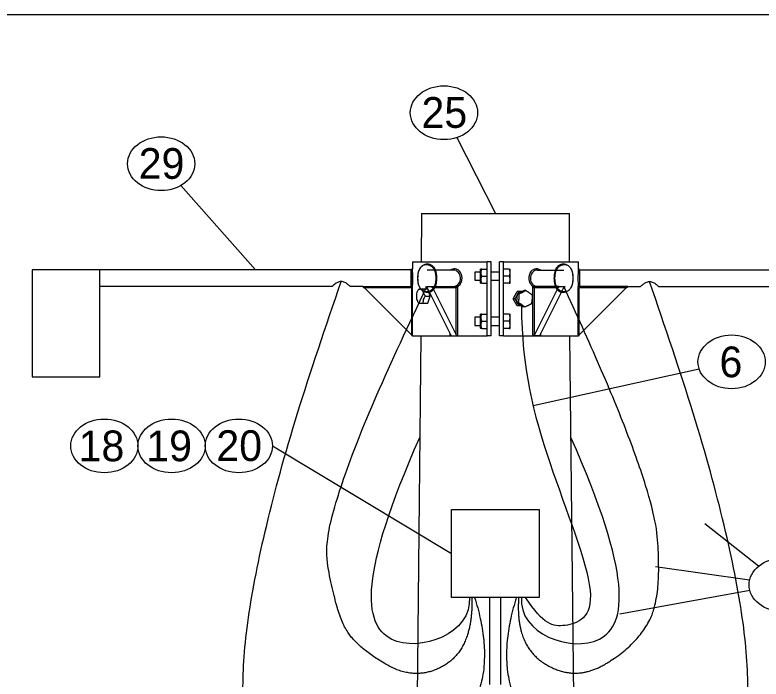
# Model space of a CAD drawing. Extents: x 99862 to 104211, y 98939 to 102076.
# Drawn here: x 101620.5 to 102008.9, y 101729.8 to 102075.5 of the extents above; entities that cross this region are included whole.
import ezdxf

# ---------------------------------------------------------------- set-up
doc = ezdxf.new("R2010")
doc.units = 0
for name, color, linetype in [('Level 1', 7, 'Continuous'), ('Level 11', 7, 'Continuous'), ('Level 15', 7, 'Continuous'), ('Level 2', 7, 'Continuous'), ('Level 20', 7, 'Continuous'), ('Level 3', 7, 'Continuous'), ('Level 4', 7, 'Continuous'), ('Level 7', 7, 'Continuous'), ('Level 8', 7, 'Continuous'), ('Level 9', 7, 'Continuous')]:
    doc.layers.add(name, color=color, linetype=linetype)

msp = doc.modelspace()

# ---------------------------------------------------------------- linework, layer by layer
at = {"layer": 'Level 1'}
for p, q in [((101832.05, 101972.17), (101831.95, 101947.03)), ((101832.05, 101972.17), (101909.09, 101972.17)), ((101909.19, 101947.03), (101909.09, 101972.17)), ((101831.83, 101908.51), (101827.97, 101553.5)), ((101913.17, 101553.5), (101909.31, 101908.51))]:
    msp.add_line(p, q, dxfattribs=at)
msp.add_lwpolyline([(99862, 99999.5), (103151, 99999.5), (103151, 102075.5), (99862, 102075.5)], close=True, dxfattribs=at)
at = {"layer": 'Level 11'}
for points, degree in [([(101859.74, 101772.33), (101884.78, 101693.2), (101689.65, 101651.83), (101790.32, 101936.72)], 2), ([(101881.51, 101772.33), (101856.36, 101693.2), (102051.49, 101651.83), (101950.83, 101936.72)], 2), ([(101858.36, 101772.33), (101858.98, 101746.11), (101829.7, 101728.16), (101798.23, 101746.36), (101787.55, 101764.66), (101778.43, 101817.11), (101834.87, 101934.19)], 2), ([(101882.71, 101772.33), (101880.76, 101747.64), (101911.44, 101728.16), (101942.91, 101746.36), (101957.57, 101772.16), (101952.13, 101835.35), (101906.16, 101934.19)], 2), ([(101884.15, 101924.06), (101884.15, 101891.84), (101896.5, 101843.69), (101929.3, 101764.2), (101905.32, 101755.78), (101895.6, 101758), (101886.26, 101772.33)], 3), ([(101857.02, 101772.33), (101858.73, 101753.77), (101803.63, 101732.32), (101799.57, 101784.11), (101831.25, 101855.61)], 3), ([(101884.12, 101772.33), (101882.41, 101753.77), (101937.51, 101732.32), (101941.57, 101784.11), (101909.89, 101855.61)], 3)]:
    msp.add_open_spline(points, degree=degree, dxfattribs=at)
at = {"layer": 'Level 15'}
for p, q in [((101850.42, 102011.63), (101870.57, 101972.17)), ((101706.78, 101986.65), (101745.76, 101942.73)), ((101976.65, 101891.16), (101890.19, 101872.03)), ((101754.53, 101851.16), (101847.74, 101795.16)), ((102007.48, 101788.47), (101979.58, 101810.64)), ((102002.91, 101781.22), (101953.92, 101788.27)), ((102003.06, 101775.81), (101935.37, 101763.54))]:
    msp.add_line(p, q, dxfattribs=at)
at = {"layer": 'Level 2'}
for p, q in [((101827.35, 101947.03), (101866.31, 101947.03)), ((101827.35, 101947.03), (101827.35, 101943.27)), ((101866.31, 101908.51), (101866.31, 101947.03)), ((101868.44, 101947.03), (101866.31, 101947.03)), ((101868.44, 101908.51), (101868.44, 101947.03)), ((101874.83, 101947.03), (101872.7, 101947.03)), ((101872.7, 101908.51), (101872.7, 101947.03)), ((101874.83, 101908.51), (101874.83, 101947.03)), ((101874.83, 101947.03), (101913.79, 101947.03)), ((101913.79, 101943.27), (101913.79, 101947.03)), ((101827.39, 101908.51), (101866.31, 101908.51)), ((101868.44, 101908.51), (101866.31, 101908.51)), ((101874.83, 101908.51), (101872.7, 101908.51)), ((101874.83, 101908.51), (101913.75, 101908.51))]:
    msp.add_line(p, q, dxfattribs=at)
for points in [[(101827.41, 101934.19), (101827.41, 101934.22), (101827.42, 101934.26), (101827.48, 101934.93), (101827.57, 101936.02), (101827.63, 101938.44), (101827.61, 101939.78), (101827.49, 101941.96), (101827.41, 101942.79), (101827.36, 101943.21), (101827.35, 101943.26), (101827.36, 101943.26)], [(101913.79, 101943.27), (101913.78, 101943.27), (101913.74, 101942.86), (101913.61, 101941.32), (101913.54, 101940.11), (101913.51, 101937.59), (101913.56, 101936.31), (101913.66, 101934.87), (101913.7, 101934.48), (101913.73, 101934.19)]]:
    msp.add_open_spline(points, degree=3, dxfattribs=at)
at = {"layer": 'Level 20'}
for centre in [(101843.8, 102024.59), (101696.61, 101998.05), (101993.52, 101894.89), (101667.03, 101851.16), (101702.03, 101851.16), (101737.03, 101851.16), (102020.15, 101778.82)]:
    msp.add_ellipse(centre, major_axis=(-17.5, 0), ratio=0.8, dxfattribs=at)
at = {"layer": 'Level 3'}
for p, q in [((101802.3, 101933.56), (101826.89, 101908.98)), ((101834.98, 101934.19), (101837.53, 101934.19)), ((101837.81, 101933.58), (101850.15, 101908.9)), ((101903.33, 101933.58), (101890.99, 101908.91)), ((101903.61, 101934.19), (101906.16, 101934.19)), ((101938.84, 101933.56), (101914.25, 101908.98)), ((101847.58, 101908.51), (101850.35, 101908.51)), ((101850.31, 101908.59), (101850.35, 101908.51)), ((101893.56, 101908.51), (101890.79, 101908.51))]:
    msp.add_line(p, q, dxfattribs=at)
for points in [[(101801.68, 101934.19), (101801.68, 101934.19), (101801.68, 101934.18)], [(101834.77, 101934.19), (101834.74, 101934.19), (101847.58, 101908.51)], [(101906.4, 101934.19), (101906.4, 101934.19), (101893.56, 101908.51)], [(101939.46, 101934.19), (101939.46, 101934.19), (101939.46, 101934.18)]]:
    msp.add_lwpolyline(points, dxfattribs=at)
at = {"layer": 'Level 4'}
for p, q in [((101664.73, 101934.19), (101664.73, 101942.73)), ((101826.82, 101942.73), (101664.73, 101942.73)), ((101826.82, 101934.19), (101826.82, 101942.71)), ((101848.69, 101942.71), (101834.98, 101942.71)), ((101892.44, 101942.71), (101906.16, 101942.71)), ((102076.41, 101942.71), (101914.32, 101942.71)), ((101785.6, 101934.19), (101664.73, 101934.19)), ((101801.68, 101934.19), (101795.03, 101934.19)), ((101939.46, 101934.19), (101946.12, 101934.19)), ((101955.55, 101934.19), (102076.41, 101934.19))]:
    msp.add_line(p, q, dxfattribs=at)
msp.add_lwpolyline([(101664.73, 101942.73), (101629.43, 101942.73), (101629.43, 101887.1), (101664.73, 101887.1)], close=True, dxfattribs=at)
for centre, major_axis, ratio, start_param, end_param in [((101848.69, 101938.44), (0, -4.27), 0.864412, 0.086361, 3.141601), ((101892.45, 101938.45), (0, -4.26), 0.866025, 3.217899, 6.283177), ((101892.45, 101938.45), (0, -4.26), 0.866025, 3.141593, 3.217899)]:
    msp.add_ellipse(centre, major_axis=major_axis, ratio=ratio, start_param=start_param, end_param=end_param, dxfattribs=at)
for points, degree in [([(101839.9, 101938.45), (101839.9, 101946.98), (101830.06, 101946.98), (101830.06, 101938.45), (101830.06, 101929.93), (101839.9, 101929.93), (101839.9, 101938.45)], 4), ([(101830.26, 101938.45), (101830.26, 101930.27), (101839.71, 101930.27), (101839.71, 101938.45), (101839.71, 101946.63), (101830.26, 101946.63), (101830.26, 101938.45)], 4), ([(101901.24, 101938.45), (101901.24, 101929.93), (101911.08, 101929.93), (101911.08, 101938.45), (101911.08, 101946.98), (101901.24, 101946.98), (101901.24, 101938.45)], 4), ([(101910.88, 101938.45), (101910.88, 101946.63), (101901.43, 101946.63), (101901.43, 101938.45), (101901.43, 101930.27), (101910.88, 101930.27), (101910.88, 101938.45)], 4), ([(101795.03, 101934.19), (101795.04, 101934.19), (101795.04, 101934.19), (101795.04, 101934.19), (101794.9, 101934.31), (101794.42, 101934.73), (101794.08, 101935.02), (101793.25, 101935.64), (101792.75, 101935.98), (101791.63, 101936.52), (101790.98, 101936.72), (101789.65, 101936.72), (101788.99, 101936.52), (101787.87, 101935.98), (101787.38, 101935.64), (101786.14, 101934.71), (101785.6, 101934.19), (101785.6, 101934.19)], 3), ([(101946.11, 101934.19), (101946.11, 101934.19), (101946.11, 101934.19), (101946.11, 101934.19), (101946.24, 101934.31), (101946.72, 101934.73), (101947.07, 101935.02), (101947.9, 101935.64), (101948.39, 101935.98), (101949.51, 101936.52), (101950.16, 101936.72), (101951.5, 101936.72), (101952.14, 101936.52), (101953.27, 101935.98), (101953.76, 101935.65), (101955.01, 101934.71), (101955.55, 101934.19), (101955.55, 101934.19)], 3)]:
    msp.add_open_spline(points, degree=degree, dxfattribs=at)
at = {"layer": 'Level 7'}
for p, q in [((101859.85, 101941.64), (101859.85, 101937.42)), ((101862.9, 101941.64), (101859.85, 101941.64)), ((101862.96, 101943.24), (101862.9, 101943.17)), ((101862.9, 101935.89), (101862.9, 101943.17)), ((101863.46, 101943.24), (101866.31, 101943.24)), ((101872.7, 101941.64), (101868.44, 101941.64)), ((101877.68, 101943.24), (101874.83, 101943.24)), ((101878.24, 101943.17), (101878.18, 101943.24)), ((101878.24, 101935.89), (101878.24, 101943.17)), ((101859.85, 101937.42), (101859.85, 101937.42)), ((101859.85, 101937.42), (101862.9, 101937.42)), ((101863.46, 101939.53), (101866.31, 101939.53)), ((101868.44, 101937.42), (101872.7, 101937.42)), ((101877.68, 101939.53), (101874.83, 101939.53)), ((101833, 101932.86), (101835.39, 101932.86)), ((101836.58, 101929.18), (101835.39, 101932.86)), ((101862.9, 101935.89), (101862.96, 101935.82)), ((101863.46, 101935.82), (101866.31, 101935.82)), ((101877.68, 101935.82), (101874.83, 101935.82)), ((101878.18, 101935.82), (101878.24, 101935.89)), ((101829.99, 101931.67), (101829.93, 101931.56)), ((101834.18, 101929.18), (101836.58, 101929.18)), ((101835.45, 101925.45), (101836.58, 101929.18)), ((101879.89, 101927.77), (101881.92, 101931.48)), ((101881.91, 101930.21), (101881.57, 101925.95)), ((101885.59, 101932.03), (101881.91, 101930.21)), ((101882.79, 101930.21), (101881.91, 101930.21)), ((101882.8, 101931.48), (101881.92, 101931.48)), ((101886.47, 101932.03), (101885.59, 101932.03)), ((101829.93, 101926.68), (101829.98, 101926.59)), ((101830.73, 101925.38), (101833.13, 101925.38)), ((101833.05, 101925.45), (101835.45, 101925.45)), ((101833.13, 101925.38), (101835.45, 101925.45)), ((101880.76, 101927.77), (101879.89, 101927.77)), ((101881.92, 101924.06), (101879.89, 101927.77)), ((101882.45, 101925.95), (101881.57, 101925.95)), ((101881.57, 101925.95), (101884.92, 101923.5)), ((101882.8, 101924.06), (101881.92, 101924.06)), ((101885.79, 101923.5), (101884.92, 101923.5)), ((101859.85, 101918.12), (101859.85, 101913.9)), ((101862.9, 101918.12), (101859.85, 101918.12)), ((101862.96, 101919.72), (101862.9, 101919.65)), ((101862.9, 101912.37), (101862.9, 101919.65)), ((101863.46, 101919.72), (101866.31, 101919.72)), ((101872.7, 101918.12), (101868.44, 101918.12)), ((101877.68, 101919.72), (101874.83, 101919.72)), ((101878.24, 101919.65), (101878.18, 101919.72)), ((101878.24, 101912.37), (101878.24, 101919.65)), ((101859.85, 101913.9), (101859.85, 101913.9)), ((101859.85, 101913.9), (101862.9, 101913.9)), ((101863.46, 101916.01), (101866.31, 101916.01)), ((101868.44, 101913.9), (101872.7, 101913.9)), ((101877.68, 101916.01), (101874.83, 101916.01)), ((101862.9, 101912.37), (101862.96, 101912.3)), ((101863.46, 101912.3), (101866.31, 101912.3)), ((101877.68, 101912.3), (101874.83, 101912.3)), ((101878.18, 101912.3), (101878.24, 101912.37))]:
    msp.add_line(p, q, dxfattribs=at)
for points in [[(101863.46, 101943.24), (101863.16, 101943.24), (101862.96, 101943.24), (101862.96, 101943.24), (101862.96, 101943.24), (101862.96, 101943.24)], [(101863.46, 101943.24), (101863.16, 101942.65), (101862.96, 101942.02), (101862.96, 101940.75), (101863.16, 101940.12), (101863.46, 101939.53)], [(101877.68, 101943.24), (101877.97, 101943.24), (101878.18, 101943.24), (101878.18, 101943.24), (101878.18, 101943.24), (101878.18, 101943.24)], [(101877.68, 101943.24), (101877.98, 101942.65), (101878.18, 101942.02), (101878.18, 101940.75), (101877.98, 101940.12), (101877.68, 101939.53)], [(101863.46, 101939.53), (101863.16, 101938.94), (101862.96, 101938.32), (101862.96, 101937.04), (101863.16, 101936.41), (101863.46, 101935.82)], [(101877.68, 101939.53), (101877.98, 101938.94), (101878.18, 101938.32), (101878.18, 101937.04), (101877.98, 101936.41), (101877.68, 101935.82)], [(101830.68, 101932.8), (101830.25, 101932.2), (101829.89, 101931.57), (101829.5, 101930.29), (101829.48, 101929.65), (101829.54, 101929.06)], [(101830.68, 101932.8), (101830.79, 101932.81), (101831.01, 101932.82), (101831.82, 101932.84), (101832.38, 101932.85), (101833, 101932.86)], [(101834.18, 101929.18), (101833.75, 101929.77), (101833.38, 101930.39), (101832.97, 101931.65), (101832.94, 101932.27), (101833, 101932.86)], [(101863.46, 101935.82), (101863.16, 101935.82), (101862.96, 101935.82), (101862.96, 101935.82), (101862.96, 101935.82), (101862.96, 101935.82)], [(101877.68, 101935.82), (101877.97, 101935.82), (101878.18, 101935.82), (101878.18, 101935.82), (101878.18, 101935.82), (101878.18, 101935.82)], [(101829.54, 101929.06), (101829.49, 101928.48), (101829.52, 101927.85), (101829.92, 101926.59), (101830.3, 101925.97), (101830.73, 101925.38)], [(101833.05, 101925.45), (101832.99, 101926.04), (101833.01, 101926.67), (101833.39, 101927.95), (101833.76, 101928.59), (101834.18, 101929.18)], [(101880.76, 101927.77), (101880.97, 101928.06), (101881.17, 101928.36), (101881.47, 101928.83), (101881.56, 101928.98), (101881.71, 101929.22), (101881.75, 101929.3), (101881.82, 101929.41), (101881.83, 101929.44), (101881.85, 101929.48)], [(101882.34, 101930.43), (101882.37, 101930.47), (101882.39, 101930.52), (101882.45, 101930.64), (101882.52, 101930.8), (101882.65, 101931.1), (101882.74, 101931.33), (101882.8, 101931.48)], [(101882.79, 101930.21), (101882.8, 101929.87), (101882.81, 101929.53), (101882.81, 101929), (101882.81, 101928.82), (101882.8, 101928.54), (101882.79, 101928.45), (101882.78, 101928.26), (101882.76, 101927.99), (101882.72, 101927.53), (101882.67, 101927.17), (101882.63, 101926.9), (101882.6, 101926.72), (101882.53, 101926.37), (101882.48, 101926.12), (101882.45, 101925.95)], [(101886.47, 101932.03), (101886.22, 101931.89), (101885.96, 101931.74), (101885.54, 101931.51), (101885.4, 101931.44), (101885.17, 101931.32), (101885.1, 101931.28), (101884.94, 101931.2), (101884.71, 101931.08), (101884.3, 101930.89), (101883.97, 101930.73), (101883.72, 101930.62), (101883.55, 101930.54), (101883.21, 101930.39), (101882.95, 101930.28), (101882.79, 101930.21)], [(101884.47, 101931.48), (101884.46, 101931.48), (101884.28, 101931.48), (101883.91, 101931.48), (101883.45, 101931.48), (101883.17, 101931.48), (101882.98, 101931.48), (101882.89, 101931.48), (101882.8, 101931.48)], [(101886.47, 101932.03), (101886.55, 101931.99), (101886.7, 101931.89), (101887.01, 101931.69), (101887.4, 101931.44), (101887.85, 101931.13), (101888.15, 101930.92), (101888.33, 101930.79), (101888.4, 101930.74), (101888.54, 101930.63), (101888.79, 101930.45), (101889.11, 101930.19), (101889.42, 101929.94), (101889.65, 101929.74), (101889.76, 101929.64), (101889.82, 101929.59)], [(101889.48, 101925.33), (101889.55, 101925.67), (101889.61, 101926.01), (101889.7, 101926.54), (101889.72, 101926.72), (101889.75, 101927), (101889.76, 101927.09), (101889.78, 101927.28), (101889.81, 101927.55), (101889.83, 101928.01), (101889.84, 101928.37), (101889.84, 101928.64), (101889.84, 101928.82), (101889.84, 101929.17), (101889.82, 101929.42), (101889.82, 101929.59)], [(101830.73, 101925.38), (101830.85, 101925.39), (101831.07, 101925.4), (101831.88, 101925.43), (101832.44, 101925.44), (101833.05, 101925.45)], [(101881.61, 101926.47), (101881.54, 101926.6), (101881.46, 101926.73), (101881.32, 101926.94), (101881.22, 101927.09), (101881.02, 101927.4), (101880.87, 101927.62), (101880.76, 101927.77)], [(101882.8, 101924.06), (101882.68, 101924.36), (101882.56, 101924.66), (101882.34, 101925.12), (101882.27, 101925.28), (101882.17, 101925.47), (101882.15, 101925.5), (101882.14, 101925.53)], [(101882.45, 101925.95), (101882.52, 101925.9), (101882.68, 101925.8), (101882.99, 101925.6), (101883.38, 101925.35), (101883.83, 101925.04), (101884.12, 101924.83), (101884.31, 101924.7), (101884.38, 101924.65), (101884.52, 101924.54), (101884.76, 101924.36), (101885.09, 101924.1), (101885.39, 101923.85), (101885.63, 101923.65), (101885.74, 101923.55), (101885.79, 101923.5)], [(101885.79, 101923.5), (101886.13, 101923.65), (101886.47, 101923.8), (101886.97, 101924.02), (101887.13, 101924.1), (101887.38, 101924.22), (101887.46, 101924.26), (101887.63, 101924.34), (101887.87, 101924.46), (101888.25, 101924.65), (101888.54, 101924.8), (101888.75, 101924.92), (101888.89, 101925), (101889.16, 101925.15), (101889.35, 101925.26), (101889.48, 101925.33)], [(101884.15, 101924.06), (101884.07, 101924.06), (101883.81, 101924.06), (101883.45, 101924.06), (101883.17, 101924.06), (101882.98, 101924.06), (101882.89, 101924.06), (101882.8, 101924.06)], [(101863.46, 101919.72), (101863.16, 101919.72), (101862.96, 101919.72), (101862.96, 101919.72), (101862.96, 101919.72), (101862.96, 101919.72)], [(101863.46, 101919.72), (101863.16, 101919.13), (101862.96, 101918.5), (101862.96, 101917.23), (101863.16, 101916.6), (101863.46, 101916.01)], [(101877.68, 101919.72), (101877.97, 101919.72), (101878.18, 101919.72), (101878.18, 101919.72), (101878.18, 101919.72), (101878.18, 101919.72)], [(101877.68, 101919.72), (101877.98, 101919.13), (101878.18, 101918.5), (101878.18, 101917.23), (101877.98, 101916.6), (101877.68, 101916.01)], [(101863.46, 101916.01), (101863.16, 101915.42), (101862.96, 101914.79), (101862.96, 101913.52), (101863.16, 101912.89), (101863.46, 101912.3)], [(101877.68, 101916.01), (101877.98, 101915.42), (101878.18, 101914.79), (101878.18, 101913.52), (101877.98, 101912.89), (101877.68, 101912.3)], [(101863.46, 101912.3), (101863.16, 101912.3), (101862.96, 101912.3), (101862.96, 101912.3), (101862.96, 101912.3), (101862.96, 101912.3)], [(101877.68, 101912.3), (101877.97, 101912.3), (101878.18, 101912.3), (101878.18, 101912.3), (101878.18, 101912.3), (101878.18, 101912.3)]]:
    msp.add_open_spline(points, degree=3, dxfattribs=at)
at = {"layer": 'Level 8'}
for p, q in [((101847.74, 101817.98), (101893.39, 101817.98)), ((101847.74, 101772.33), (101847.74, 101817.98)), ((101893.39, 101817.98), (101893.39, 101772.33)), ((101893.39, 101772.33), (101847.74, 101772.33)), ((101867.72, 101726.87), (101867.72, 101772.33)), ((101873.42, 101726.88), (101873.42, 101772.33))]:
    msp.add_line(p, q, dxfattribs=at)
at = {"layer": 'Level 9'}
for p, q in [((101826.82, 101942.73), (101826.82, 101942.73)), ((101826.82, 101942.73), (101826.82, 101934.19)), ((101914.32, 101942.73), (101914.32, 101934.19)), ((101801.68, 101934.19), (101827.42, 101934.19)), ((101802.21, 101933.56), (101826.89, 101933.56)), ((101826.89, 101933.56), (101826.89, 101909.05)), ((101827.42, 101909.05), (101827.42, 101934.19)), ((101834.29, 101934.19), (101834.74, 101934.19)), ((101834.82, 101933.56), (101835.05, 101933.56)), ((101837.53, 101934.19), (101838.42, 101934.19)), ((101837.96, 101933.56), (101850.28, 101933.56)), ((101838.42, 101934.19), (101850.73, 101934.19)), ((101850.14, 101909.05), (101850.14, 101933.56)), ((101850.73, 101934.19), (101850.8, 101934.19)), ((101851.05, 101909.05), (101851.05, 101933.65)), ((101890.1, 101908.96), (101890.09, 101933.65)), ((101890.41, 101934.19), (101890.34, 101934.19)), ((101902.72, 101934.19), (101890.41, 101934.19)), ((101890.86, 101933.56), (101903.18, 101933.56)), ((101891, 101908.96), (101891, 101933.56)), ((101903.61, 101934.19), (101902.72, 101934.19)), ((101906.09, 101933.56), (101906.32, 101933.56)), ((101906.4, 101934.19), (101906.85, 101934.19)), ((101938.93, 101934.19), (101913.72, 101934.19)), ((101913.72, 101909.05), (101913.72, 101934.19)), ((101914.25, 101933.56), (101938.93, 101933.56)), ((101914.25, 101909.05), (101914.25, 101933.56)), ((101939.46, 101934.19), (101938.93, 101934.19)), ((101846.87, 101909.92), (101846.87, 101909.05)), ((101894.27, 101908.96), (101894.27, 101909.92))]:
    msp.add_line(p, q, dxfattribs=at)
for centre, radius, start, end in [((101827.35, 101942.73), 0.535, 89.9931, 180), ((101913.79, 101942.73), 0.535, 0, 90), ((101802.21, 101934.1), 0.535, 170.1039, 270), ((101834.82, 101934.1), 0.535, 170.1039, 270), ((101837.96, 101934.1), 0.535, 242.1626, 270), ((101850.28, 101934.1), 0.535, 270, 286.0934), ((101850.28, 101934.1), 0.535, 318.8794, 0), ((101850.28, 101934.1), 0.535, 0, 9.8961), ((101890.86, 101934.1), 0.535, 170.1039, 218.0108), ((101890.86, 101934.1), 0.535, 249.5109, 270), ((101903.18, 101934.1), 0.535, 270, 297.8374), ((101906.32, 101934.1), 0.535, 270, 0), ((101906.32, 101934.1), 0.535, 0, 9.8961), ((101938.93, 101934.1), 0.535, 270, 0), ((101938.93, 101934.1), 0.535, 0, 9.8961), ((101827.42, 101909.05), 0.535, 180, 266.9168), ((101847.41, 101909.05), 0.535, 180, 265.2479), ((101890.55, 101908.96), 0.448, 180, 360), ((101893.82, 101908.96), 0.448, 239.7701, 360), ((101893.73, 101909.05), 0.535, 359.987, 0), ((101913.72, 101909.05), 0.535, 273.1075, 0.0285), ((101850.61, 101909.12), 0.614, 241.3741, 266.7538)]:
    msp.add_arc(centre, radius, start, end, dxfattribs=at)
for centre, major_axis, ratio, start_param, end_param in [((101837.77, 101934.1), (0, -0.489), 0.5, 4.523352, 6.025039), ((101837.96, 101934.1), (0, -0.535), 0.86577, 6.283183, 8.026701), ((101850.43, 101933.88), (-0.313, -0.218), 0.69336, 1.551205, 1.917054), ((101890.71, 101933.88), (0.313, -0.218), 0.69336, 4.287136, 4.73198), ((101903.18, 101934.1), (0, 0.535), 0.86577, 1.398077, 3.141595), ((101903.37, 101934.1), (0, 0.489), 0.5, 3.39973, 4.901426), ((101850.38, 101909.05), (0, -0.48), 0.5, 4.712389, 5.994837)]:
    msp.add_ellipse(centre, major_axis=major_axis, ratio=ratio, start_param=start_param, end_param=end_param, dxfattribs=at)
for points in [[(101853.2, 101938.45), (101853.21, 101938.77), (101853.09, 101939.99), (101851.88, 101942.74), (101848.96, 101943.65), (101847.27, 101942.89), (101846.99, 101942.71)], [(101894.15, 101942.71), (101893.22, 101943.25), (101890.56, 101943.64), (101888.38, 101941.27), (101888.02, 101939.38), (101887.95, 101938.92), (101887.94, 101938.61), (101887.94, 101938.45)], [(101850.81, 101934.12), (101851.87, 101934.71), (101852.81, 101935.94), (101853.12, 101937.52), (101853.19, 101937.99), (101853.2, 101938.3), (101853.2, 101938.45)], [(101887.94, 101938.45), (101887.93, 101938.13), (101888.05, 101936.92), (101888.79, 101935.22), (101889.89, 101934.36), (101890.33, 101934.12)], [(101850.42, 101933.58), (101850.45, 101933.59), (101850.47, 101933.6), (101850.5, 101933.61), (101850.52, 101933.62), (101850.55, 101933.64), (101850.58, 101933.65)], [(101851.05, 101933.65), (101851.05, 101933.7), (101851.04, 101933.74), (101851.03, 101933.79), (101851.02, 101933.85), (101851, 101933.9), (101850.97, 101933.95), (101850.94, 101934), (101850.9, 101934.05), (101850.86, 101934.08), (101850.84, 101934.09), (101850.83, 101934.11), (101850.81, 101934.12)], [(101890.09, 101933.65), (101890.09, 101933.7), (101890.09, 101933.74), (101890.1, 101933.79), (101890.12, 101933.85), (101890.14, 101933.9), (101890.17, 101933.95), (101890.2, 101934), (101890.24, 101934.05), (101890.28, 101934.08), (101890.3, 101934.1), (101890.31, 101934.11), (101890.33, 101934.12)], [(101890.68, 101933.6), (101890.67, 101933.6), (101890.65, 101933.6), (101890.64, 101933.61), (101890.62, 101933.62), (101890.59, 101933.64), (101890.56, 101933.65)], [(101827.39, 101908.51), (101827.39, 101908.51), (101827.39, 101908.51), (101827.39, 101908.51), (101827.4, 101908.52), (101827.4, 101908.53), (101827.4, 101908.55), (101827.4, 101908.57), (101827.41, 101908.61), (101827.41, 101908.65), (101827.41, 101908.69), (101827.41, 101908.73), (101827.42, 101908.79), (101827.42, 101908.84), (101827.42, 101908.9), (101827.42, 101908.96), (101827.42, 101908.99), (101827.42, 101909.02), (101827.42, 101909.05)], [(101850.57, 101908.51), (101850.59, 101908.51), (101850.62, 101908.51), (101850.64, 101908.52), (101850.69, 101908.53), (101850.74, 101908.54), (101850.79, 101908.57), (101850.84, 101908.6), (101850.88, 101908.64), (101850.92, 101908.68), (101850.95, 101908.72), (101850.98, 101908.77), (101851.01, 101908.83), (101851.03, 101908.88), (101851.04, 101908.94), (101851.05, 101909), (101851.05, 101909.02), (101851.05, 101909.03), (101851.05, 101909.05)], [(101913.72, 101909.05), (101913.72, 101909.01), (101913.72, 101908.98), (101913.72, 101908.94), (101913.72, 101908.88), (101913.72, 101908.83), (101913.72, 101908.77), (101913.73, 101908.72), (101913.73, 101908.68), (101913.73, 101908.64), (101913.73, 101908.6), (101913.74, 101908.57), (101913.74, 101908.55), (101913.74, 101908.53), (101913.74, 101908.51), (101913.75, 101908.51), (101913.75, 101908.51), (101913.75, 101908.51), (101913.75, 101908.51)], [(101847.56, 101908.55), (101847.55, 101908.54), (101847.54, 101908.54), (101847.53, 101908.54), (101847.48, 101908.52), (101847.43, 101908.51), (101847.38, 101908.51), (101847.37, 101908.51), (101847.36, 101908.51), (101847.35, 101908.51)]]:
    msp.add_open_spline(points, degree=3, dxfattribs=at)

# ---------------------------------------------------------------- texts
at = {"layer": 'Level 20'}
for s, p in [('25', (101832.1, 102016.72)), ('29', (101684.91, 101990.18)), ('6', (101987.21, 101886.89)), ('18', (101653.65, 101843.16)), ('19', (101688.86, 101843.16)), ('20', (101725.33, 101843.29))]:
    msp.add_text(s, height=16, dxfattribs=at).set_placement(p)

doc.saveas('drawing.dxf')
